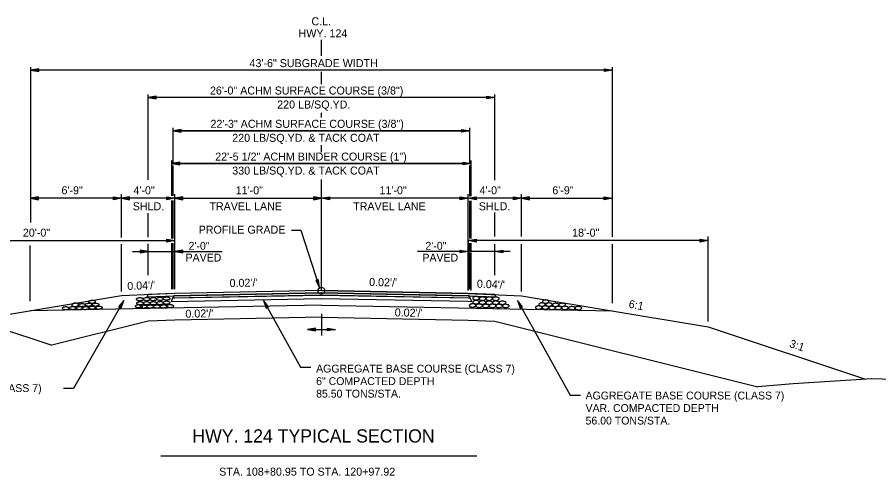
# Model space of a CAD drawing. Extents: x 1824008 to 1828864, y 689441 to 689870.
# Drawn here: x 1828762.4 to 1828827, y 689778.1 to 689812.5 of the extents above; entities that cross this region are included whole.
import ezdxf

# ---------------------------------------------------------------- set-up
doc = ezdxf.new("R2010")
doc.units = 0
for name, color, linetype in [('1', 7, 'Continuous'), ('19', 7, 'Continuous'), ('42', 7, 'Continuous'), ('Level 1', 7, 'Continuous'), ('R_Draft', 7, 'Continuous'), ('R_Horz Alg', 7, 'Continuous')]:
    doc.layers.add(name, color=color, linetype=linetype)

# ---------------------------------------------------------------- blocks, each defined once
blk = doc.blocks.new('ROCKS')
at = {"layer": '1'}
blk.add_spline([(0.013, 0.06), (0.053, 0.053), (0.107, 0.033), (0.133, 0.013), (0.133, -0.007), (0.12, -0.033), (0.107, -0.04), (0.073, -0.053), (0.033, -0.067), (0.013, -0.067), (-0.02, -0.06), (-0.06, -0.053), (-0.087, -0.047), (-0.113, -0.02), (-0.113, -0.007), (-0.107, 0.02), (-0.087, 0.033), (-0.067, 0.047), (-0.033, 0.053), (-0.02, 0.06), (0.013, 0.06)], degree=3, dxfattribs=at)
blk = doc.blocks.new('4TO1 ABC')
at = {"layer": '1', "xscale": 0.1312491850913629, "yscale": 0.1312491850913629, "rotation": 180}
for p in [(0.00175, -0.00875), (-0.03325, -0.0385), (-0.016625, -0.023625), (0, -0.0385), (0.018375, -0.023625), (0.034125, -0.04025), (0.051625, -0.025375), (0.06475, -0.04025), (0.098, -0.04025), (0.133, -0.041125)]:
    blk.add_blockref('ROCKS', p, dxfattribs=at)

msp = doc.modelspace()

# ---------------------------------------------------------------- linework, layer by layer
at = {"layer": '1'}
for p, q in [((1828764.015, 689808.62), (1828763.415, 689808.515)), ((1828763.415, 689808.515), (1828764.015, 689808.41)), ((1828764.015, 689808.565), (1828763.575, 689808.53)), ((1828763.575, 689808.5), (1828764.015, 689808.46)), ((1828764.015, 689808.41), (1828764.015, 689808.62)), ((1828806.455, 689808.41), (1828806.455, 689808.62)), ((1828806.455, 689808.62), (1828807.055, 689808.515)), ((1828806.455, 689808.565), (1828806.895, 689808.53)), ((1828807.055, 689808.515), (1828806.455, 689808.41)), ((1828806.895, 689808.5), (1828806.455, 689808.46)), ((1828772.815, 689806.564), (1828772.215, 689806.459)), ((1828772.215, 689806.459), (1828772.815, 689806.354)), ((1828772.815, 689806.509), (1828772.375, 689806.474)), ((1828772.375, 689806.444), (1828772.815, 689806.404)), ((1828772.815, 689806.354), (1828772.815, 689806.564)), ((1828797.624, 689806.354), (1828797.624, 689806.564)), ((1828797.624, 689806.564), (1828798.224, 689806.459)), ((1828797.624, 689806.509), (1828798.064, 689806.474)), ((1828798.224, 689806.459), (1828797.624, 689806.354)), ((1828798.064, 689806.444), (1828797.624, 689806.404)), ((1828774.695, 689804.064), (1828774.095, 689803.959)), ((1828774.095, 689803.959), (1828796.345, 689803.959)), ((1828774.095, 689803.959), (1828774.695, 689803.854)), ((1828774.695, 689804.009), (1828774.255, 689803.974)), ((1828774.255, 689803.944), (1828774.695, 689803.904)), ((1828774.695, 689803.854), (1828774.695, 689804.064)), ((1828795.745, 689803.854), (1828795.745, 689804.064)), ((1828795.745, 689804.064), (1828796.345, 689803.959)), ((1828795.745, 689804.009), (1828796.185, 689803.974)), ((1828796.345, 689803.959), (1828795.745, 689803.854)), ((1828796.185, 689803.944), (1828795.745, 689803.904)), ((1828774.59, 689801.606), (1828773.99, 689801.501)), ((1828773.99, 689801.501), (1828796.449, 689801.501)), ((1828773.99, 689801.501), (1828774.59, 689801.396)), ((1828774.095, 689799.073), (1828774.095, 689801.361)), ((1828774.59, 689801.551), (1828774.15, 689801.516)), ((1828774.15, 689801.486), (1828774.59, 689801.446)), ((1828774.59, 689801.396), (1828774.59, 689801.606)), ((1828795.849, 689801.396), (1828795.849, 689801.606)), ((1828795.849, 689801.606), (1828796.449, 689801.501)), ((1828795.849, 689801.551), (1828796.289, 689801.516)), ((1828796.449, 689801.501), (1828795.849, 689801.396)), ((1828796.289, 689801.486), (1828795.849, 689801.446)), ((1828796.345, 689799.064), (1828796.345, 689801.361)), ((1828770.22, 689795.96), (1828770.22, 689799.196)), ((1828770.22, 689795.96), (1828770.22, 689799.196)), ((1828774.22, 689792.066), (1828774.22, 689799.196)), ((1828796.22, 689792.066), (1828796.22, 689799.196)), ((1828764.008, 689799.001), (1828763.408, 689798.896)), ((1828763.408, 689798.896), (1828764.008, 689798.791)), ((1828764.008, 689798.946), (1828763.568, 689798.911)), ((1828763.568, 689798.881), (1828764.008, 689798.841)), ((1828764.008, 689798.791), (1828764.008, 689799.001)), ((1828769.62, 689798.791), (1828769.62, 689799.001)), ((1828769.62, 689799.001), (1828770.22, 689798.896)), ((1828769.62, 689798.946), (1828770.06, 689798.911)), ((1828770.22, 689798.896), (1828769.62, 689798.791)), ((1828770.06, 689798.881), (1828769.62, 689798.841)), ((1828770.82, 689799.001), (1828770.22, 689798.896)), ((1828770.22, 689798.896), (1828770.82, 689798.791)), ((1828770.82, 689798.946), (1828770.38, 689798.911)), ((1828770.38, 689798.881), (1828770.82, 689798.841)), ((1828770.82, 689798.791), (1828770.82, 689799.001)), ((1828773.62, 689798.791), (1828773.62, 689799.001)), ((1828773.62, 689799.001), (1828774.22, 689798.896)), ((1828773.62, 689798.946), (1828774.06, 689798.911)), ((1828774.22, 689798.896), (1828773.62, 689798.791)), ((1828774.06, 689798.881), (1828773.62, 689798.841)), ((1828773.99, 689795.89), (1828773.99, 689798.729)), ((1828774.095, 689795.89), (1828774.095, 689798.729)), ((1828774.82, 689799.001), (1828774.22, 689798.896)), ((1828774.22, 689798.896), (1828785.22, 689798.896)), ((1828774.22, 689798.896), (1828774.82, 689798.791)), ((1828774.82, 689798.946), (1828774.38, 689798.911)), ((1828774.38, 689798.881), (1828774.82, 689798.841)), ((1828774.82, 689798.791), (1828774.82, 689799.001)), ((1828775.22, 689798.896), (1828785.22, 689798.896)), ((1828775.22, 689798.896), (1828785.22, 689798.896)), ((1828784.62, 689799.001), (1828784.62, 689798.791)), ((1828785.22, 689798.896), (1828784.62, 689799.001)), ((1828784.62, 689799.001), (1828784.62, 689798.791)), ((1828785.22, 689798.896), (1828784.62, 689799.001)), ((1828785.06, 689798.911), (1828784.62, 689798.946)), ((1828785.06, 689798.911), (1828784.62, 689798.946)), ((1828784.62, 689798.791), (1828785.22, 689798.896)), ((1828784.62, 689798.791), (1828785.22, 689798.896)), ((1828784.62, 689798.841), (1828785.06, 689798.881)), ((1828784.62, 689798.841), (1828785.06, 689798.881)), ((1828785.22, 689798.896), (1828785.82, 689799.001)), ((1828785.22, 689798.896), (1828785.82, 689799.001)), ((1828795.22, 689798.896), (1828785.22, 689798.896)), ((1828785.82, 689798.791), (1828785.22, 689798.896)), ((1828796.22, 689798.896), (1828785.22, 689798.896)), ((1828785.82, 689798.791), (1828785.22, 689798.896)), ((1828785.38, 689798.911), (1828785.82, 689798.946)), ((1828785.38, 689798.911), (1828785.82, 689798.946)), ((1828785.82, 689798.841), (1828785.38, 689798.881)), ((1828785.82, 689798.841), (1828785.38, 689798.881)), ((1828785.82, 689799.001), (1828785.82, 689798.791)), ((1828785.82, 689799.001), (1828785.82, 689798.791)), ((1828795.62, 689798.791), (1828795.62, 689799.001)), ((1828795.62, 689799.001), (1828796.22, 689798.896)), ((1828795.62, 689798.946), (1828796.06, 689798.911)), ((1828796.22, 689798.896), (1828795.62, 689798.791)), ((1828796.06, 689798.881), (1828795.62, 689798.841)), ((1828796.22, 689798.896), (1828796.82, 689799.001)), ((1828796.82, 689798.791), (1828796.22, 689798.896)), ((1828796.345, 689795.89), (1828796.345, 689798.702)), ((1828796.38, 689798.911), (1828796.82, 689798.946)), ((1828796.82, 689798.841), (1828796.38, 689798.881)), ((1828796.82, 689799.001), (1828796.82, 689798.791)), ((1828799.62, 689798.791), (1828799.62, 689799.001)), ((1828799.62, 689799.001), (1828800.22, 689798.896)), ((1828799.62, 689798.946), (1828800.06, 689798.911)), ((1828800.22, 689798.896), (1828799.62, 689798.791)), ((1828800.06, 689798.881), (1828799.62, 689798.841)), ((1828800.82, 689799.001), (1828800.22, 689798.896)), ((1828800.22, 689798.896), (1828800.82, 689798.791)), ((1828800.82, 689798.946), (1828800.38, 689798.911)), ((1828800.38, 689798.881), (1828800.82, 689798.841)), ((1828800.82, 689798.791), (1828800.82, 689799.001)), ((1828806.431, 689798.791), (1828806.431, 689799.001)), ((1828806.431, 689799.001), (1828807.031, 689798.896)), ((1828806.431, 689798.946), (1828806.871, 689798.911)), ((1828807.031, 689798.896), (1828806.431, 689798.791)), ((1828806.871, 689798.881), (1828806.431, 689798.841)), ((1828772.22, 689795.984), (1828772.22, 689797.789)), ((1828798.22, 689796.017), (1828798.22, 689797.821)), ((1828754.22, 689795.717), (1828774.22, 689795.717)), ((1828770.22, 689791.906), (1828770.22, 689795.442)), ((1828772.22, 689793.137), (1828772.22, 689795.482)), ((1828773.62, 689795.612), (1828773.62, 689795.822)), ((1828773.62, 689795.822), (1828774.22, 689795.717)), ((1828773.62, 689795.767), (1828774.06, 689795.732)), ((1828774.22, 689795.717), (1828773.62, 689795.612)), ((1828774.06, 689795.702), (1828773.62, 689795.662)), ((1828796.22, 689795.717), (1828796.82, 689795.822)), ((1828814.22, 689795.717), (1828796.22, 689795.717)), ((1828796.82, 689795.612), (1828796.22, 689795.717)), ((1828796.38, 689795.732), (1828796.82, 689795.767)), ((1828796.82, 689795.662), (1828796.38, 689795.702)), ((1828796.82, 689795.822), (1828796.82, 689795.612)), ((1828798.22, 689793.137), (1828798.22, 689795.442)), ((1828813.62, 689795.612), (1828813.62, 689795.822)), ((1828813.62, 689795.822), (1828814.22, 689795.717)), ((1828813.62, 689795.767), (1828814.06, 689795.732)), ((1828814.22, 689795.717), (1828813.62, 689795.612)), ((1828814.06, 689795.702), (1828813.62, 689795.662)), ((1828773.99, 689792.066), (1828773.99, 689794.831)), ((1828774.095, 689792.555), (1828774.095, 689794.831)), ((1828774.095, 689792.066), (1828774.095, 689794.831)), ((1828796.345, 689792.066), (1828796.345, 689794.831)), ((1828748.155, 689793.481), (1828765.008, 689787.863)), ((1828774.22, 689791.746), (1828770.22, 689791.586)), ((1828785.22, 689791.966), (1828774.22, 689791.746)), ((1828785.22, 689791.966), (1828796.22, 689791.746)), ((1828796.22, 689791.746), (1828800.22, 689791.586)), ((1828785.22, 689790.883), (1828763.379, 689790.446)), ((1828785.22, 689790.883), (1828807.061, 689790.446)), ((1828772.22, 689789.666), (1828765.008, 689787.863)), ((1828774.22, 689789.746), (1828772.22, 689789.666)), ((1828785.22, 689789.966), (1828774.22, 689789.746)), ((1828785.22, 689789.966), (1828796.22, 689789.746)), ((1828796.22, 689789.746), (1828798.22, 689789.666)), ((1828798.22, 689789.666), (1828817.941, 689784.736)), ((1828814.22, 689789.253), (1828826.024, 689785.318)), ((1828773.166, 689779.578), (1828796.878, 689779.578))]:
    msp.add_line(p, q, dxfattribs=at)
msp.add_lwpolyline([(1828852.627, 689785.831), (1828844.044, 689785.542), (1828832.759, 689785.156), (1828826.49, 689785.349), (1828820.607, 689784.963), (1828817.941, 689784.736)], dxfattribs=at)
msp.add_circle((1828785.215, 689791.964), 0.25, dxfattribs=at)
at = {"layer": '19'}
for p, q in [((1828763.415, 689797.072), (1828763.415, 689808.74)), ((1828807.055, 689808.515), (1828763.415, 689808.515)), ((1828807.055, 689795.996), (1828807.055, 689808.74)), ((1828772.215, 689800.278), (1828772.215, 689806.684)), ((1828798.224, 689806.459), (1828772.215, 689806.459)), ((1828798.224, 689800.25), (1828798.224, 689806.684)), ((1828774.095, 689801.586), (1828774.095, 689804.184)), ((1828796.345, 689803.959), (1828774.095, 689803.959)), ((1828796.345, 689801.586), (1828796.345, 689804.184)), ((1828773.991, 689799.081), (1828773.991, 689801.726)), ((1828796.448, 689799.063), (1828796.448, 689801.726)), ((1828796.448, 689801.501), (1828773.991, 689801.501)), ((1828796.449, 689795.89), (1828796.449, 689798.702)), ((1828773.99, 689794.96), (1828773.99, 689795.523)), ((1828774.095, 689794.96), (1828774.095, 689795.523)), ((1828796.345, 689794.96), (1828796.345, 689795.523)), ((1828796.449, 689794.96), (1828796.449, 689795.523)), ((1828771.06, 689794.898), (1828777.786, 689794.898)), ((1828771.615, 689795.003), (1828771.615, 689794.793)), ((1828772.215, 689794.898), (1828771.615, 689795.003)), ((1828772.055, 689794.913), (1828771.615, 689794.948)), ((1828771.615, 689794.793), (1828772.215, 689794.898)), ((1828771.615, 689794.843), (1828772.055, 689794.883)), ((1828774.815, 689795.003), (1828774.215, 689794.898)), ((1828774.215, 689794.898), (1828774.815, 689794.793)), ((1828774.815, 689794.948), (1828774.375, 689794.913)), ((1828774.375, 689794.883), (1828774.815, 689794.843)), ((1828774.815, 689794.793), (1828774.815, 689795.003)), ((1828799.38, 689794.898), (1828792.437, 689794.898)), ((1828795.624, 689794.793), (1828795.624, 689795.003)), ((1828795.624, 689795.003), (1828796.224, 689794.898)), ((1828795.624, 689794.948), (1828796.064, 689794.913)), ((1828796.224, 689794.898), (1828795.624, 689794.793)), ((1828796.064, 689794.883), (1828795.624, 689794.843)), ((1828796.449, 689791.963), (1828796.449, 689794.831)), ((1828798.224, 689794.898), (1828798.824, 689795.003)), ((1828798.824, 689794.793), (1828798.224, 689794.898)), ((1828798.384, 689794.913), (1828798.824, 689794.948)), ((1828798.824, 689794.843), (1828798.384, 689794.883)), ((1828798.824, 689795.003), (1828798.824, 689794.793)), ((1828770.22, 689791.586), (1828754.22, 689788.919)), ((1828772.22, 689791.666), (1828772.135, 689791.496)), ((1828772.135, 689791.496), (1828774.223, 689791.579)), ((1828774.22, 689791.746), (1828772.22, 689791.666)), ((1828774.063, 689791.409), (1828773.941, 689791.158)), ((1828773.941, 689791.158), (1828785.208, 689791.382)), ((1828785.213, 689791.633), (1828774.063, 689791.409)), ((1828785.223, 689791.799), (1828774.147, 689791.577)), ((1828785.22, 689791.966), (1828774.22, 689791.746)), ((1828774.223, 689791.579), (1828785.223, 689791.799)), ((1828774.226, 689791.413), (1828785.213, 689791.633)), ((1828785.208, 689791.382), (1828785.208, 689791.383)), ((1828785.208, 689791.383), (1828785.22, 689791.383)), ((1828785.226, 689791.633), (1828785.213, 689791.633)), ((1828785.213, 689791.633), (1828785.213, 689791.633)), ((1828785.213, 689791.633), (1828785.22, 689791.633)), ((1828796.22, 689791.746), (1828785.22, 689791.966)), ((1828785.22, 689791.633), (1828785.226, 689791.633)), ((1828785.22, 689791.383), (1828785.231, 689791.383)), ((1828785.223, 689791.799), (1828796.22, 689791.579)), ((1828796.305, 689791.576), (1828785.223, 689791.799)), ((1828796.386, 689791.41), (1828785.226, 689791.633)), ((1828785.226, 689791.633), (1828785.226, 689791.633)), ((1828785.226, 689791.633), (1828796.213, 689791.413)), ((1828785.231, 689791.383), (1828785.231, 689791.382)), ((1828785.231, 689791.382), (1828796.208, 689791.163)), ((1828798.22, 689791.666), (1828796.22, 689791.746)), ((1828796.22, 689791.579), (1828798.305, 689791.496)), ((1828798.305, 689791.496), (1828798.22, 689791.666)), ((1828800.22, 689791.586), (1828814.22, 689789.253)), ((1828770.394, 689791.213), (1828766.631, 689784.612)), ((1828770.394, 689791.213), (1828770.006, 689790.743)), ((1828770.006, 689790.743), (1828770.189, 689790.64)), ((1828770.302, 689791.081), (1828770.049, 689790.719)), ((1828770.141, 689790.667), (1828770.328, 689791.067)), ((1828770.189, 689790.64), (1828770.394, 689791.213)), ((1828780.866, 689791.213), (1828783.65, 689786.221)), ((1828781.255, 689790.744), (1828780.866, 689791.213)), ((1828780.866, 689791.213), (1828781.072, 689790.64)), ((1828780.933, 689791.067), (1828781.116, 689790.665)), ((1828781.207, 689790.717), (1828780.959, 689791.081)), ((1828781.072, 689790.64), (1828781.255, 689790.744)), ((1828799.917, 689791.213), (1828803.879, 689784.109)), ((1828800.306, 689790.744), (1828799.917, 689791.213)), ((1828799.917, 689791.213), (1828800.123, 689790.64)), ((1828799.984, 689791.067), (1828800.167, 689790.665)), ((1828800.258, 689790.717), (1828800.01, 689791.081)), ((1828800.123, 689790.64), (1828800.306, 689790.744)), ((1828783.65, 689786.221), (1828784.416, 689786.221)), ((1828766.631, 689784.612), (1828765.865, 689784.612)), ((1828803.879, 689784.109), (1828804.645, 689784.109))]:
    msp.add_line(p, q, dxfattribs=at)
for points in [[(1828774.147, 689791.577), (1828774.063, 689791.409), (1828774.226, 689791.413)], [(1828796.208, 689791.163), (1828796.512, 689791.151), (1828796.386, 689791.41)], [(1828796.213, 689791.413), (1828796.386, 689791.41), (1828796.305, 689791.576)]]:
    msp.add_lwpolyline(points, dxfattribs=at)
at = {"layer": '42'}
for p, q in [((1828785.22, 689790.223), (1828785.22, 689788.59)), ((1828784.772, 689789.147), (1828784.172, 689789.042)), ((1828784.172, 689789.042), (1828784.772, 689788.937)), ((1828784.172, 689789.042), (1828786.267, 689789.042)), ((1828784.772, 689789.092), (1828784.332, 689789.057)), ((1828784.332, 689789.027), (1828784.772, 689788.987)), ((1828784.772, 689788.937), (1828784.772, 689789.147)), ((1828785.667, 689788.937), (1828785.667, 689789.147)), ((1828785.667, 689789.147), (1828786.267, 689789.042)), ((1828785.667, 689789.092), (1828786.107, 689789.057)), ((1828786.267, 689789.042), (1828785.667, 689788.937)), ((1828786.107, 689789.027), (1828785.667, 689788.987))]:
    msp.add_line(p, q, dxfattribs=at)
at = {"layer": 'R_Draft'}
for p, q in [((1828785.22, 689809.588), (1828785.22, 689810.784)), ((1828785.22, 689807.47), (1828785.22, 689808.376)), ((1828785.22, 689804.961), (1828785.22, 689805.299)), ((1828785.22, 689802.35), (1828785.22, 689802.883)), ((1828785.22, 689791.966), (1828785.22, 689800.298)), ((1828800.22, 689796.017), (1828800.22, 689799.196)), ((1828800.22, 689796.017), (1828800.22, 689799.196)), ((1828770.22, 689798.896), (1828763.408, 689798.896)), ((1828774.22, 689798.896), (1828770.22, 689798.896)), ((1828775.22, 689798.896), (1828785.22, 689798.896)), ((1828784.62, 689799.001), (1828784.62, 689798.791)), ((1828785.22, 689798.896), (1828784.62, 689799.001)), ((1828785.06, 689798.911), (1828784.62, 689798.946)), ((1828784.62, 689798.791), (1828785.22, 689798.896)), ((1828784.62, 689798.841), (1828785.06, 689798.881)), ((1828785.22, 689798.896), (1828785.82, 689799.001)), ((1828795.22, 689798.896), (1828785.22, 689798.896)), ((1828785.82, 689798.791), (1828785.22, 689798.896)), ((1828785.38, 689798.911), (1828785.82, 689798.946)), ((1828785.82, 689798.841), (1828785.38, 689798.881)), ((1828785.82, 689799.001), (1828785.82, 689798.791)), ((1828800.22, 689798.896), (1828796.22, 689798.896)), ((1828800.22, 689798.896), (1828807.031, 689798.896)), ((1828800.22, 689791.906), (1828800.22, 689795.442)), ((1828785.002, 689792.782), (1828784.803, 689792.717)), ((1828784.803, 689792.717), (1828785.088, 689792.179)), ((1828784.848, 689792.728), (1828785.024, 689792.328)), ((1828785.049, 689792.333), (1828784.952, 689792.761)), ((1828785.088, 689792.179), (1828785.002, 689792.782))]:
    msp.add_line(p, q, dxfattribs=at)
msp.add_lwpolyline([(1828782.988, 689796.505), (1828783.677, 689796.507), (1828785.088, 689792.179)], dxfattribs=at)
at = {"layer": 'R_Horz Alg'}
for p, q in [((1828796.22, 689791.966), (1828796.22, 689796.322)), ((1828814.22, 689789.64), (1828814.22, 689796.017)), ((1828763.379, 689791.166), (1828763.379, 689795.348)), ((1828796.22, 689795.717), (1828796.22, 689792.029)), ((1828807.055, 689791.023), (1828807.055, 689795.442))]:
    msp.add_line(p, q, dxfattribs=at)

# ---------------------------------------------------------------- block references
at = {"layer": '19', "xscale": 14.999970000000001, "yscale": -14.999970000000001, "rotation": 180}
msp.add_blockref('4TO1 ABC', (1828768.022, 689791.255), dxfattribs=at)
at = {"layer": '19', "xscale": 14.999970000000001, "yscale": 14.999970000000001}
msp.add_blockref('4TO1 ABC', (1828802.027, 689791.268), dxfattribs=at)
at = {"layer": 'Level 1', "xscale": 2.0116542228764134}
for p, yscale, rotation in [((1828771.617, 689791.328), -2.0116542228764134, 179.66979900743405), ((1828772.126, 689791.339), -2.0116542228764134, 179.66979900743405), ((1828772.629, 689791.334), -2.0116542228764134, 179.66979900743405), ((1828773.126, 689791.35), -2.0116542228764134, 179.66979900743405), ((1828773.626, 689791.378), -2.0116542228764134, 179.66979900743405), ((1828796.797, 689791.399), 2.0116542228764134, 0.3302009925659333), ((1828797.283, 689791.367), 2.0116542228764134, 0.3302009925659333), ((1828797.784, 689791.367), 2.0116542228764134, 0.3302009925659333), ((1828798.286, 689791.363), 2.0116542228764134, 0.3302009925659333), ((1828766.736, 689790.902), 2.011654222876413, 1.8621306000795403), ((1828771.546, 689790.8), -2.0116542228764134, 179.66979900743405), ((1828771.641, 689791.021), -2.0116542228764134, 179.66979900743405), ((1828771.909, 689790.771), -2.0116542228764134, 179.66979900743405), ((1828772.132, 689791.029), -2.0116542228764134, 179.66979900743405), ((1828772.399, 689790.779), -2.0116542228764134, 179.66979900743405), ((1828772.635, 689791.024), -2.0116542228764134, 179.66979900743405), ((1828772.903, 689790.774), -2.0116542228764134, 179.66979900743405), ((1828773.131, 689791.04), -2.0116542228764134, 179.66979900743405), ((1828773.399, 689790.79), -2.0116542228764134, 179.66979900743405), ((1828773.622, 689791.067), -2.0116542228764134, 179.66979900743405), ((1828773.895, 689790.81), -2.0116542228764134, 179.66979900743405), ((1828796.54, 689790.857), 2.0116542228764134, 0.3302009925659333), ((1828796.792, 689791.107), 2.0116542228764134, 0.3302009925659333), ((1828797.036, 689790.837), 2.0116542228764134, 0.3302009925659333), ((1828797.283, 689791.08), 2.0116542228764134, 0.3302009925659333), ((1828797.532, 689790.821), 2.0116542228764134, 0.3302009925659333), ((1828797.78, 689791.064), 2.0116542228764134, 0.3302009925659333), ((1828798.035, 689790.826), 2.0116542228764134, 0.3302009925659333), ((1828798.283, 689791.069), 2.0116542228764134, 0.3302009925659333), ((1828798.526, 689790.818), 2.0116542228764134, 0.3302009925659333), ((1828798.773, 689791.061), 2.0116542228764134, 0.3302009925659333), ((1828799.027, 689790.82), 2.0116542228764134, 0.3302009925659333), ((1828803.253, 689790.902), 2.0116542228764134, 0.3302009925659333), ((1828804.468, 689790.659), 2.0116542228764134, 0.3302009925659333)]:
    msp.add_blockref('ROCKS', p, dxfattribs=dict(at, yscale=yscale, rotation=rotation))

# ---------------------------------------------------------------- texts
at = {"layer": '1'}
for s, height, p in [('C.L.', 0.6, (1828784.473, 689811.877)), ('HWY. 124', 0.6, (1828783.509, 689810.977)), ('43\'-6" SUBGRADE WIDTH', 0.6, (1828779.826, 689808.74)), ('26\'-0" ACHM SURFACE COURSE (3/8")', 0.6, (1828776.862, 689806.684)), ('220 LB/SQ.YD.', 0.6, (1828781.903, 689805.634)), ('22\'-3" ACHM SURFACE COURSE (3/8")', 0.6, (1828776.9, 689804.184)), ('220 LB/SQ.YD. & TACK COAT', 0.6, (1828778.532, 689803.134)), ('22\'-5 1/2" ACHM BINDER COURSE (1")', 0.6, (1828777.255, 689801.726)), ('330 LB/SQ.YD. & TACK COAT', 0.6, (1828778.532, 689800.676)), ('SHLD.', 0.6, (1828771.067, 689797.996)), ('2\'-0"', 0.59, (1828793.021, 689795.033)), ('PAVED', 0.59, (1828792.798, 689794.148))]:
    msp.add_text(s, height=height, dxfattribs=at).set_placement(p)
for s, height, rotation, p in [('2\'-0"', 0.59, 360, (1828775.258, 689795.033)), ('PAVED', 0.59, 360, (1828775.035, 689794.148)), ("0.04'/'", 0.6, 2.29061, (1828770.672, 689792.01)), ("0.02'/'", 0.6, 1.14576, (1828778.337, 689792.233)), ("0.02'/'", 0.6, 358.85424, (1828788.793, 689792.317)), ('6:1', 0.6, 348.57628, (1828808.228, 689790.701)), ("0.02'/'", 0.6, 1.14576, (1828775.023, 689789.929)), ("0.02'/'", 0.6, 358.85424, (1828790.712, 689790.035)), ('3:1', 0.6, 341.56505, (1828820.271, 689787.742)), ('HWY. 124 TYPICAL SECTION ', 0.98999, 359.99538, (1828775.542, 689780.566))]:
    msp.add_text(s, height=height, rotation=rotation, dxfattribs=at).set_placement(p)
at = {"layer": '19'}
for s, p in [('AGGREGATE BASE COURSE (CLASS 7)', (1828784.823, 689785.818)), ('AGGREGATE BASE COURSE (CLASS 7)', (1828749.327, 689784.354)), ('6" COMPACTED DEPTH', (1828784.823, 689784.878)), ('85.50 TONS/STA.', (1828784.823, 689783.938)), ('AGGREGATE BASE COURSE (CLASS 7)', (1828805.029, 689783.797)), ('VAR. COMPACTED DEPTH', (1828805.029, 689782.857)), ('56.00 TONS/STA.', (1828805.029, 689781.917))]:
    msp.add_text(s, height=0.59001, rotation=360, dxfattribs=at).set_placement(p)
at = {"layer": 'R_Draft'}
for s, p in [('6\'-9"', (1828765.725, 689799.196)), ('4\'-0"', (1828771.121, 689799.196)), ('11\'-0"', (1828778.791, 689799.196)), ('11\'-0"', (1828789.574, 689799.196)), ('4\'-0"', (1828797.078, 689799.196)), ('6\'-9"', (1828802.536, 689799.196)), ('TRAVEL LANE', (1828776.819, 689797.996)), ('TRAVEL LANE', (1828787.601, 689797.996)), ('SHLD.', (1828797.024, 689797.996)), ('20\'-0"', (1828762.828, 689796.017)), ('PROFILE GRADE', (1828776.011, 689796.239)), ('18\'-0"', (1828804.022, 689796.017))]:
    msp.add_text(s, height=0.6, dxfattribs=at).set_placement(p)
for s, rotation, p in [("0.04'/'", 357.70939, (1828796.872, 689792.189)), ('STA. 108+80.95 TO STA. 120+97.92', 359.99538, (1828777.551, 689778.078))]:
    msp.add_text(s, height=0.6, rotation=rotation, dxfattribs=at).set_placement(p)

doc.saveas('drawing.dxf')
